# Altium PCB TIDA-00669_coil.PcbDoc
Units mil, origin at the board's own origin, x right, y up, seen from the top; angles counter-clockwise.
Board outline 2510.03 x 1760.03 mil, 2 copper layers (Top Layer, Bottom Layer), stack 62 mil thick; 13 components, 5 nets, 9 pads, 0 vias.
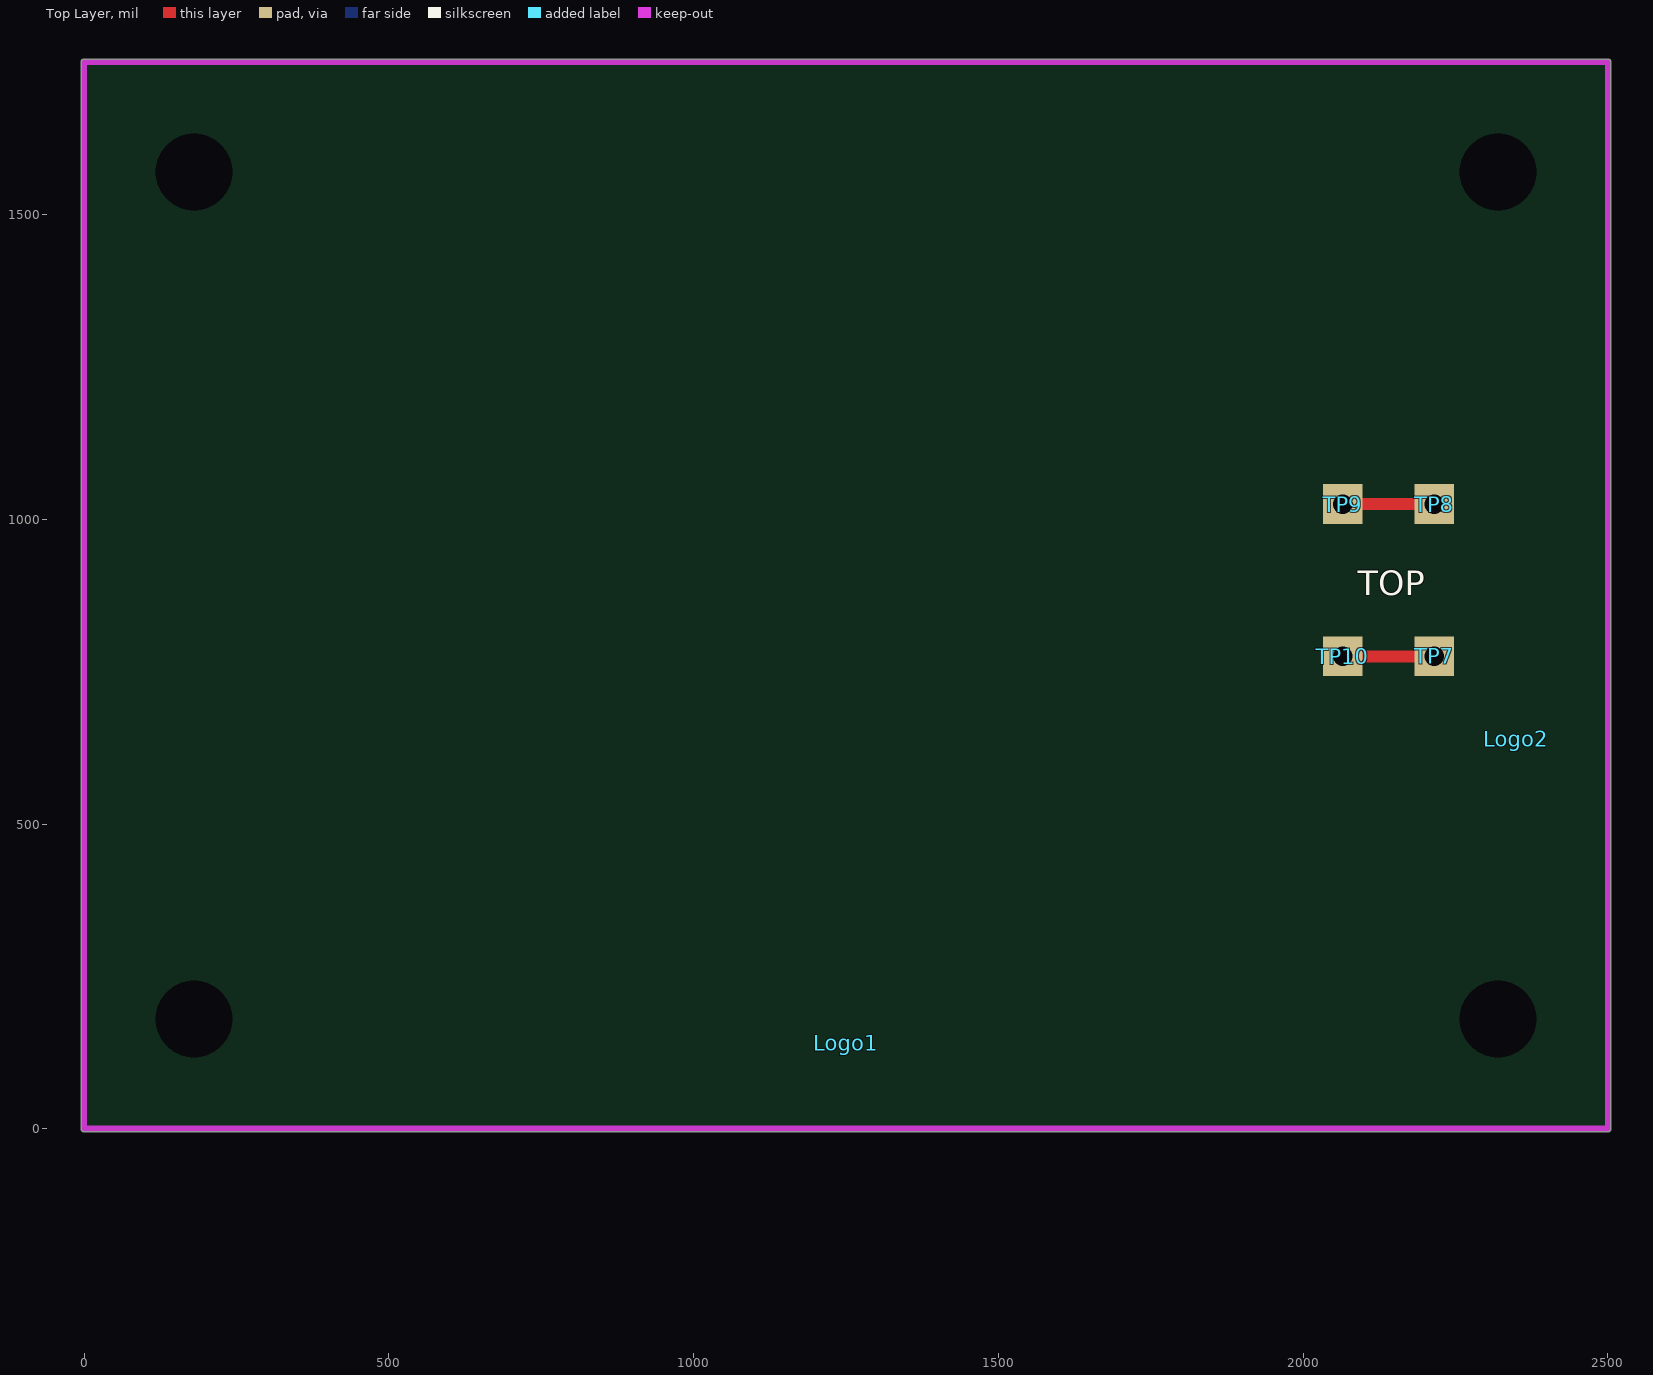
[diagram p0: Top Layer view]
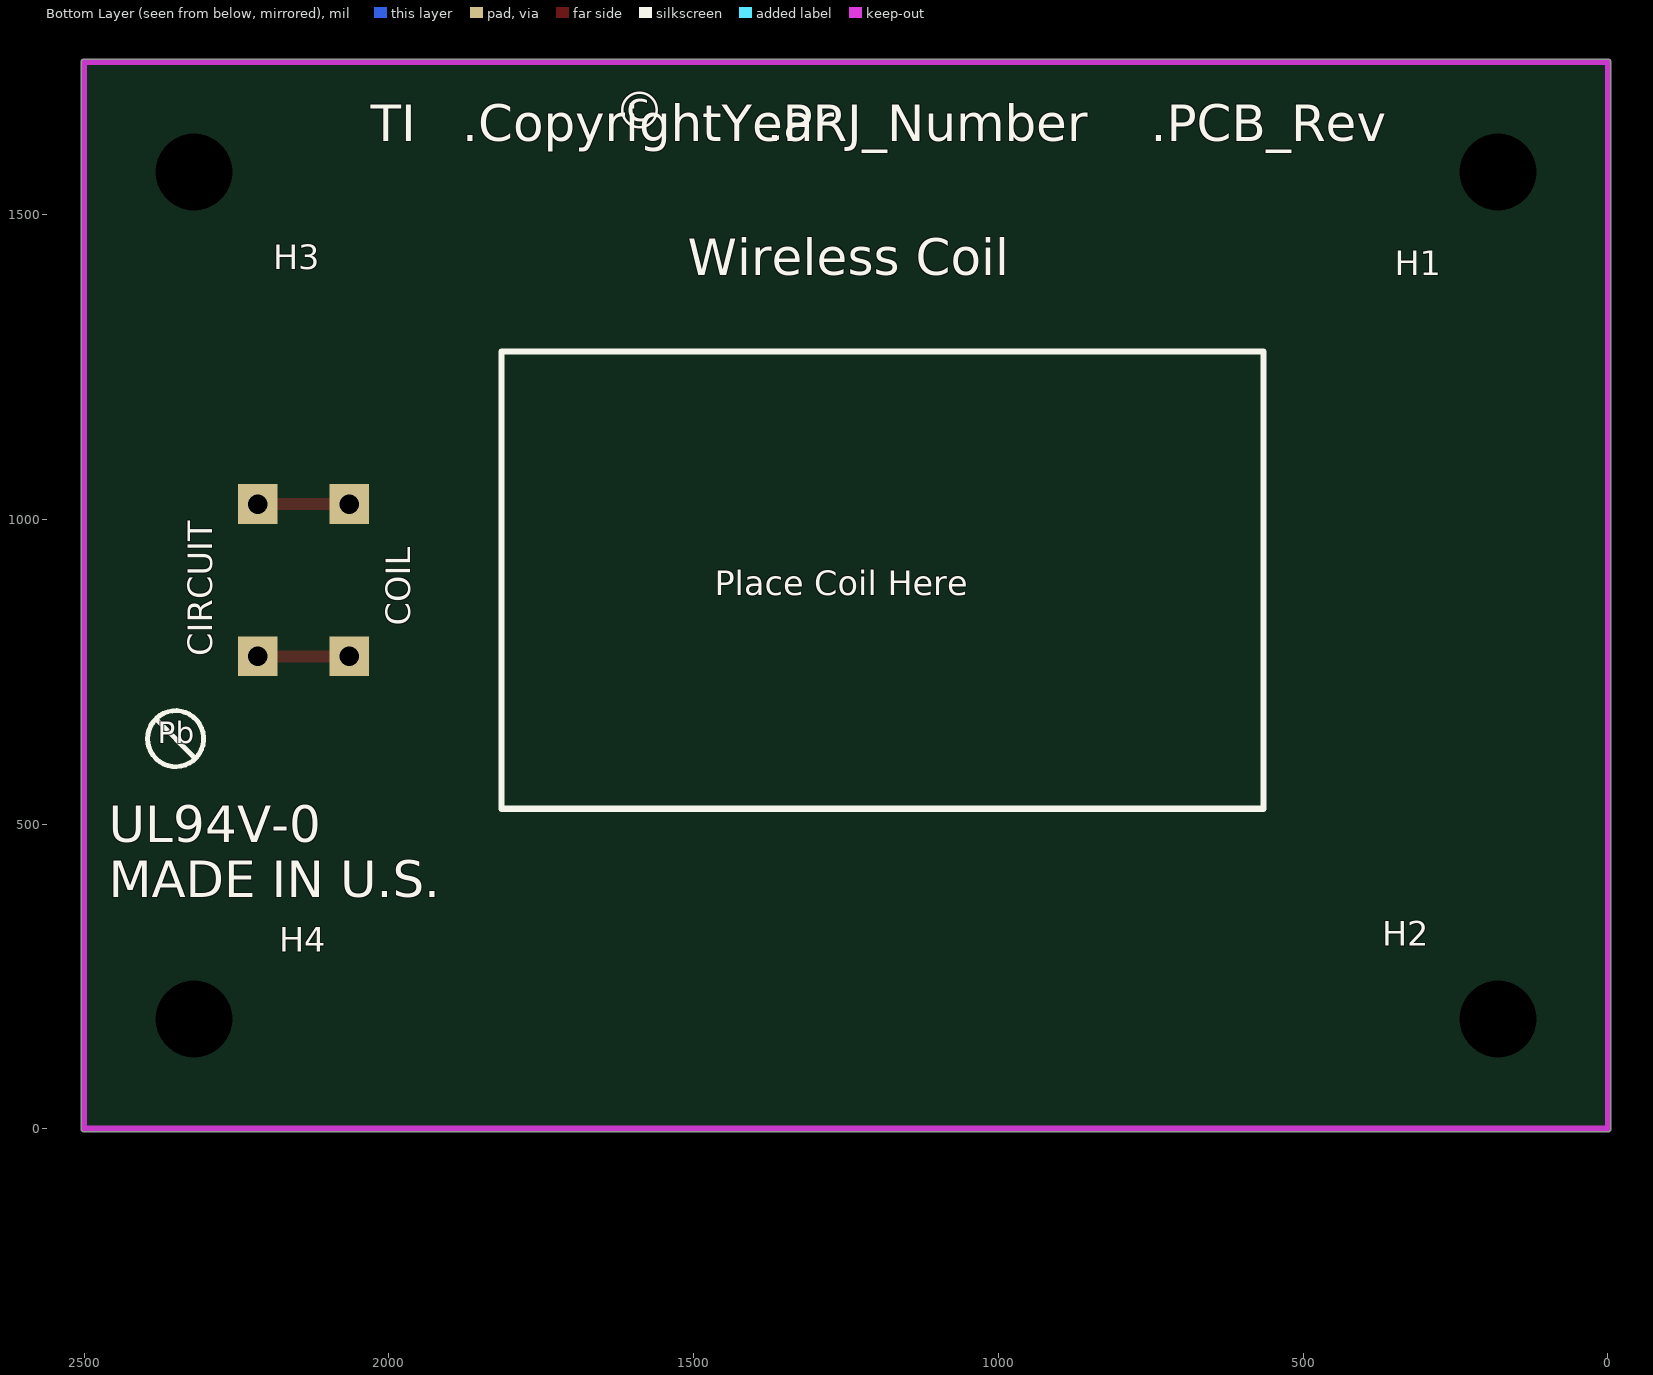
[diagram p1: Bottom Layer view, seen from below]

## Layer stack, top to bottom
Top Solder: solder mask 0.4, Solder Resist, Dk 3.5
Top Layer: signal copper 1.4
Dielectric1: core 59.2, FR-4, Dk 4.8
Bottom Layer: signal copper 1.4
Bottom Solder: solder mask 0.4, Solder Resist, Dk 3.5

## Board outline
0,-5.02 cw(c0,0) -5.01,0 -5.01,1750 cw(c0,1750) 0,1755.01 2500,1755.01 cw(c2500,1750) 2505.01,1750 2505.01,0 cw(c2500,0) 2500,-5.02

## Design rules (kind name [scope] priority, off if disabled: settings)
AcuteAngle [All] p1: minimum=4.50000000000000E+0001 checktracksonly=FALSE
AssemblyTestPointUsage [All] p1: valid=2
Clearance Clearance_Keepouts [((IsTrack Or IsArc) And Not InPoly) And IsFree and IsKeepOut vs ((IsTrack Or IsArc) And Not InPoly) And IsFree and IsKeepOut] p1: gap=0
Clearance Clearance_BoardEdge_MountingHoles [OnCopper and InComponentClass('Mounting Holes') vs IsKeepOut] p2: gap=40
Clearance Clearance_BoardEdge_Poly [OnCopper and InPoly vs IsKeepOut] p3: gap=25
Clearance Clearance_BoardEdge [OnCopper and Not InComponentClass('Logo') and not InComponentClass('FiducialMark') and not InRegion(1000,500,4000,800) and Not IsKeepout vs IsKeepOut] p4: gap=40
Clearance Clearance_Poly [InPolygon] p5: gap=12
Clearance [All] p6: gap=8
ComponentClearance ComponentClearance_MountingHoles_FiducialMarks [InComponentClass('Mounting Holes') vs InComponentClass('FiducialMark')] p1: gap=50 collisioncheckmode=3 verticalgap=10 showdistances=FALSE
ComponentClearance ComponentClearance_Shunt [InComponentClass('Header') vs InComponentClass('Shunt')] p2: gap=0 collisioncheckmode=3 verticalgap=0 showdistances=FALSE
ComponentClearance ComponentClearance_Logo [InComponentClass('Logo')] p3: gap=50 collisioncheckmode=3 verticalgap=10 showdistances=FALSE
ComponentClearance ComponentClearance_ScrewToNut [(HasFootprint('NY PMS 440 0025 PH')) vs (HasFootprint('Keystone_1902C'))] p4: gap=5 collisioncheckmode=3 verticalgap=10 showdistances=FALSE
ComponentClearance ComponentClearance_MountingHoles [InComponentClass('Mounting Holes')] p5: gap=20 collisioncheckmode=3 verticalgap=100000 showdistances=FALSE
ComponentClearance ComponentClearance_SmallPassives [HasFootprint('0201*') or HasFootprint('0402*') or HasFootprint('0508') or HasFootprint('0603*') or HasFootprint('0612') or HasFootprint('0805*') or HasFootprint('0815*') or HasFootprint('0830*') or HasFootprint('1206*') or HasFootprint('1210*') or HasFootprint('1808*') or HasFootprint('1812*') or HasFootprint('1825*') or HasFootprint('2010*') or HasFootprint('2220*') or HasFootprint('2225*') or HasFootprint('2512*') or HasFootprint('2728*') or HasFootprint('3518*') vs HasFootprint('0201*') or HasFootprint('0402*') or HasFootprint('0508') or HasFootprint('0603*') or HasFootprint('0612') or HasFootprint('0805*') or HasFootprint('0815*') or HasFootprint('0830*') or HasFootprint('1206*') or HasFootprint('1210*') or HasFootprint('1808*') or HasFootprint('1812*') or HasFootprint('1825*') or HasFootprint('2010*') or HasFootprint('2220*') or HasFootprint('2225*') or HasFootprint('2512*') or HasFootprint('2728*') or HasFootprint('3518*')] p6: gap=12 collisioncheckmode=3 verticalgap=12 showdistances=FALSE
ComponentClearance ComponentClearance_THtoSMT [IsThruComponent vs IsSMTComponent] p7: gap=12 collisioncheckmode=3 verticalgap=12 showdistances=FALSE
ComponentClearance ComponentClearance_THtoTH [IsThruComponent vs IsThruComponent] p8: gap=12 collisioncheckmode=3 verticalgap=12 showdistances=FALSE
ComponentClearance [All] p9: gap=12 collisioncheckmode=3 verticalgap=12 showdistances=FALSE
DiffPairsRouting [All] p1: maxlimit=100 minlimit=10 mostfreqgap=10 toplayer_minwidth=15 toplayer_maxwidth=15 toplayer_prefwidth=15 bottomlayer_minwidth=15 bottomlayer_maxwidth=15 bottomlayer_prefwidth=15 maxuncoupledlength=1000
FabricationTestPointUsage TestPointUsage [All] p1: valid=2 allowmultiple=FALSE
FabricationTestpoint Testpoint [All] p1: side=3 testpointundercomponent=TRUE minsize=40 maxsize=100 preferedsize=60 minholesize=0 maxholesize=40 preferedholesize=32 testpointgrid=1 allowsidetop=TRUE allowsidebottom=TRUE usegrid=TRUE gridtolerance=0.01
FanoutControl Fanout_LCC [IsLCC] p1: bgadir=Out bgaviamode=Centered fanoutstyle=Auto fanoutdirection=Alternating viagrid=1 // Fanout_LCC (Default Rule)
FanoutControl Fanout_BGA [IsBGA] p2: bgadir=Out bgaviamode=Centered fanoutstyle=Auto fanoutdirection=Alternating viagrid=1 // Fanout_BGA (Default Rule)
FanoutControl Fanout_Default [All] p4: bgadir=Out bgaviamode=Centered fanoutstyle=Auto fanoutdirection=Alternating viagrid=1 // Fanout_Default (Default Rule)
FanoutControl Fanout_Small [(CompPinCount < 5)] p5: bgadir=Out bgaviamode=Centered fanoutstyle=Auto fanoutdirection=OutThenIn viagrid=1 // Fanout_Small (Default Rule)
HoleSize [All] p1: absolutevalues=TRUE maxlimit=251 minlimit=8 maxpercent=80.000 minpercent=20.000
MinimumAnnularRing MinimumAnnularRing_ThermalPadVias [IsVia and InAnyComponent] p1: minimumring=5.91
MinimumAnnularRing [All] p2: minimumring=9
MinimumSolderMaskSliver MinimumSolderMaskSliver_Logo [InComponentClass('Logo') vs InComponentClass('Logo')] p1: minsoldermaskwidth=0.7
MinimumSolderMaskSliver [All] p2: minsoldermaskwidth=3.94
PlaneConnect [All] p1: planeconnectstyle=Relief reliefexpansion=10 reliefentries=4 reliefconductorwidth=10 reliefairgap=10
PolygonConnect [All] p1: connectstyle=Relief reliefconductorwidth=10 reliefentries=4 polygonreliefangle="90 Angle" airgapwidth=10
RoutingVias ThermalPadVias [IsVia and InAnyComponent] p1: holewidth=7.87 width=19.68 viastyle="Through Hole" minholewidth=7.87 minwidth=19.68 maxholewidth=12.99 maxwidth=23.62
RoutingVias [All] p2: holewidth=16 width=34 viastyle="Through Hole" minholewidth=7.87 minwidth=26 maxholewidth=40 maxwidth=65
SilkToBoardRegionClearance [Not ((IsComment or IsDesignator) And (Hide <> 'False')) and not InRegion(1000,500,4000,800)] p1:
SilkToSilkClearance SilkToSilkClearance_Pb-FreeLogo [(HasFootprint('Pb-Free_Overlay_Medium') OR HasFootprint('Pb-Free_Overlay_Small')) vs (HasFootprint('Pb-Free_Overlay_Medium') OR HasFootprint('Pb-Free_Overlay_Small'))] p1: silktosilkclearance=0
SilkToSilkClearance [All] p2: silktosilkclearance=5
SilkToSolderMaskClearance "Silk to Solder Mask Opening" [All] p1: minsilkscreentomaskgap=1 clearancetoexposedcopper=FALSE
SolderMaskExpansion [All] p1: expansion=1.97
UnpouredPolygon [All] p1: allowunpoured=FALSE
Width [All] p1: maxlimit=100 minlimit=6 preferedwidth=10 checkconnectedcopper=TRUE
14 further rules are at their usual default settings.

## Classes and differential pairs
component class PR2220E1_hdw: ZZ2 ZZ3 ZZ4
component class AssemblyNote: ZZ2 ZZ3 ZZ4

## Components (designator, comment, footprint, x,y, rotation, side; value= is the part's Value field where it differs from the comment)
H1 "Comment" "NY PMS 440 0025 PH" 180,1570 r180 bottom
H2 "Comment" "NY PMS 440 0025 PH" 180,180 r180 bottom
H3 "Comment" "NY PMS 440 0025 PH" 2320,1570 r180 bottom
H4 "Comment" "NY PMS 440 0025 PH" 2320,180 r180 bottom
Logo1 "Texas Instruments" TI_Stacked_SolderMask_Small 1250,140 r180 top
Logo2 "Pb-Free Symbol" Pb-Free_Overlay_Small 2350,640 r180 top
TP7 "STD" TP-032 2215,775 r0 top
TP8 "STD" TP-032 2215,1025 r0 top
TP9 "STD" TP-032 2065,1025 r0 top
TP10 "STD" TP-032 2065,775 r0 top
ZZ2 "These assemblies are ESD sensitive, ESD precautions shall be observed." AssemblyNote 185,3829.11 r0 top
ZZ3 "These assemblies must be clean and free from flux and all contaminants. Use of no clean flux is not acceptable." AssemblyNote 185,3740.56 r0 top
ZZ4 "These assemblies must comply with workmanship standards IPC-A-610 Class 2, unless otherwise specified." AssemblyNote 185,3652 r0 top

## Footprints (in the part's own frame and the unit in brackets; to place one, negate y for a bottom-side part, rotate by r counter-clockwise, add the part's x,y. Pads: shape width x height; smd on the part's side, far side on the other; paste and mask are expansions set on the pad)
AssemblyNote [mil] "Assembly Note"
"NY PMS 440 0025 PH" [mm] "4-40 nylon screw and mounting hole"
  round 0 hole 3.2 unplated: 1(0,0)
  body extent -3.3,-3.3 3.3,3.3, height 2.69
Pb-Free_Overlay_Small [mil]
TI_Stacked_SolderMask_Small [mil]
  rect 900x250 on Bottom Overlay paste-125 mask-125: 0(0,0)
TP-032 [mil]
  rect 65x65 hole 32: 1(0,0)

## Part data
Logo1: library part TI_Logo, "Texas Instrument Corporate Signature"
Logo2: library part Pb-Free
TP7 TP8 TP9 TP10: "Test Point, O.032 Hole"
ZZ2 ZZ3 ZZ4: library part AssemblyNote

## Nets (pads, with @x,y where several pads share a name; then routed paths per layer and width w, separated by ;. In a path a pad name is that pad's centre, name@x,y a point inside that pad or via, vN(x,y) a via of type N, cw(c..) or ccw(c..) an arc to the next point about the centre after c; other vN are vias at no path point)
+3.3V: 
+5V: 
GND: 
VBAT_OK: 
VBAT_OK_ALT: 
pads on no net: H1.1 H2.1 H3.1 H4.1 Logo1.0 TP7.1 TP8.1 TP9.1 TP10.1
copper on no net: | length 310
  Top Layer w20: 2065,1025 2145,1025 2215,1025 ; 2080,775 2160,775 ; 2150,775 2230,775

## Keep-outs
Keep-Out Layer:
  lines w10: 0,0 2500,0 ; 0,0 0,1750 ; 0,0 2500,0 ; 0,1750 2500,1750 ; 0,1750 2500,1750 ; 2500,0 2500,1750 ; 2500,0 2500,1750
  text ".Layer_Name" at 577,-858.49 h60

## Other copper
Top Layer:
  text ".Layer_Name" at 577,-858.49 h60
Bottom Layer:
  text ".Layer_Name" at 577,-858.49 h60
Multi-Layer:
  text "VERY IMPORTANT: The only copper on PCB is for the wire holes and the coil. No extra copper is allowed." at -130,1970 h100

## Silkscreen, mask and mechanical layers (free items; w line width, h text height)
Top Overlay:
  text "TOP" at 2090,875 h40
  text ".Layer_Name" at 577,-858.49 h60
Bottom Overlay:
  lines w10: 565,525 1815,525 1815,1275 565,1275 565,525
  text ".PCB_Rev" at 750,1620 h60
  text ".PRJ_Number" at 1380,1620 h60
  text "©" at 1630,1620 h105
  text ".CopyrightYear" at 1880,1620 h60
  text "TI" at 2030,1620 h60
  text "Wireless Coil" at 1510,1400 h60
  text "Place Coil Here" at 1465,875 h40
  text "COIL" at 1965,825 h40 r270
  text "CIRCUIT" at 2290,775 h40 r270
  text "UL94V-0" at 2460,470 h60
  text "MADE IN U.S." at 2460,380 h60
  text ".Layer_Name" at 577,-858.49 h60
Top Paste:
  text ".Layer_Name" at 577,-858.49 h60
Bottom Paste:
  text ".Layer_Name" at 577,-858.49 h60
Top Solder:
  text ".Layer_Name" at 577,-858.49 h60
  text ".Layer_Name" at 577,-858.49 h60
Bottom Solder:
  text ".Layer_Name" at 577,-858.49 h60
Drill Guide:
  text ".Layer_Name" at 577,-858.49 h60
M1 Board Outline:
  lines w10: 0,0 2500,0 2500,1750 0,1750 0,0
  text ".Layer_Name" at 577,-858.49 h60
M2 Board Dimensions:
  rectangle: 0,-275 125,-150
  rectangle: 125,-400 500,-275
  lines w7: 0,-275 1000,-275 ; 0,-150 0,-400 1000,-400 1000,-150 ; 125,-400 125,-150 ; 250,-400 250,-150 ; 500,-400 500,-150 ; 750,-400 750,-150
  text ".Layer_Name" at 577,-858.49 h60
M3 3D STEP Top:
  text ".Layer_Name" at 577,-858.49 h60
M4 3D STEP Bottom:
  lines w10: 6984.8,1433.6 7005,1433.6 ; 6984.9,1152.7 7005.1,1152.7
  text ".Layer_Name" at 577,-858.49 h60
M5 Assembly Top:
  lines w10: -292,-930.17 6308,-930.17 ; -292,-726.83 6310,-726.83 ; -292,-523.5 -292,-1133.5 3713,-1133.5 6310,-1133.5 6310,-523.5 -291.5,-523.5 -291.5,-1133.5 1284,-1133.5 ; 2173,-1133.5 2173,-523.5 ; 3440,-726.83 3440,-523.5 ; 4280,-726.83 4280,-523.5 ; 4902,-1140 4902,-937.17
  text "COMPONENTS MARKED 'DNP' SHOULD NOT BE POPULATED." at 1153.5,-318.5 h60
  text "ASSEMBLY VARIANT:" at 1153,-434 h60
  text ".VariantName" at 2189,-434 h60
  text "PCB VIEWED FROM TOP SIDE" at -228.5,-655.67 h60
  text "BOARD #:" at 2248,-655.67 h60
  text ".PRJ_Number" at 2793.5,-655.67 h60
  text "REV:" at 3638,-655.67 h60
  text ".PCB_Rev" at 3929.5,-655.67 h60
  text "SVN REV:" at 4476,-655.67 h60
  text ".VersionControl_RevNumber" at 4982,-655.67 h60
  text "PLOT NAME =" at -228.5,-1064.34 h60
  text ".plot_File_Name" at 577,-1064.34 h60
  text "GENERATED    :" at 2250,-1064.34 h60
  text ".Print_Date" at 3119.5,-1064.34 h60
  text ".Print_Time" at 3848.5,-1064.34 h60
  text "TEXAS INSTRUMENTS" at 5113,-1064.34 h60
M6 Assembly Bottom:
  lines w10: -292.5,-727.33 6309.5,-727.33 ; -290.5,-930.67 6309.5,-930.67 ; 1115.5,-1140.5 1115.5,-937.67 ; 1737.5,-727.33 1737.5,-524 ; 2577.5,-727.33 2577.5,-524 ; 3844.5,-1134 3844.5,-524 ; 4733.5,-1134 6309,-1134 6309,-524 -292.5,-524 -292.5,-1134 2304.5,-1134 6309.5,-1134 6309.5,-524
  text "COMPONENTS MARKED 'DNP' SHOULD NOT BE POPULATED." at 6102,-318 h60
  text ".VariantName" at 5058,-434 h60
  text "ASSEMBLY VARIANT:" at 6097,-434 h60
  text ".VersionControl_RevNumber" at 1035.5,-656.17 h60
  text "SVN REV:" at 1541.5,-656.17 h60
  text ".PCB_Rev" at 2088,-656.17 h60
  text "REV:" at 2379.5,-656.17 h60
  text ".PRJ_Number" at 3224,-656.17 h60
  text "BOARD #:" at 3769.5,-656.17 h60
  text "PCB VIEWED FROM BOTTOM SIDE" at 6246,-656.17 h60
  text "TEXAS INSTRUMENTS" at 904.5,-1064.84 h60
  text ".Print_Time" at 2169,-1064.84 h60
  text ".Print_Date" at 2898,-1064.84 h60
  text "GENERATED    :" at 3767.5,-1064.84 h60
  text ".plot_File_Name" at 5440.5,-1064.84 h60
  text "PLOT NAME =" at 6246,-1064.84 h60
M9 Title Sheet:
  drawing of 57 lines, arcs and shapes, not listed
  text "1" at 739.84,8036.5 h70
  text "2" at 3235.5,8036.5 h70
  text "3" at 5724.84,8036.5 h70
  text "4" at 8231.51,8036.5 h70
  text "5" at 10730.5,8036.5 h70
  text "6" at 13235.5,8036.5 h70
  text "A" at -416.5,6893.5 h70
  text "A" at 14383.5,6893.5 h70
  text "B" at -416.5,4513.5 h70
  text "B" at 14383.5,4513.5 h70
  text "C" at -416.5,2138.5 h70
  text "C" at 14383.5,2138.5 h70
  text "PROJECT TITLE:" at 11343.5,277.5 h45
  text ".PRJ_Title" at 11393.5,144.17 h70
  text "DESIGNED FOR:" at 11343.5,-23.5 h45
  text ".PRJ_Customer" at 11393.5,-163.5 h70
  text "D" at -416.5,-231.5 h70
  text "D" at 14383.5,-231.5 h70
  text "FILE NAME:" at 11343.5,-323.5 h45
  text ".PCB_File_Name_No_Path" at 11393.5,-443.5 h70
  text "Texas Instruments (TI) and/or its licensors do not warrant the accuracy or completeness of this specification" at 6374,-605.34 h45
  text "ENGINEER:" at 11343.5,-613.5 h45
  text "LAYOUT BY:" at 12848.5,-613.5 h45
  text "or any information contained therein. TI and/or its licensors do not warrant that this design will meet" at 6329.01,-718 h45
  text ".PRJ_Engineer" at 11393.5,-768.49 h70
  text ".PCB_Layout" at 12899,-768.49 h70
  text "the specifications, will be suitable for your application or fit for any particular purpose, or will operate in" at 6329.01,-830.67 h45
  text ".Layer_Name" at 577,-858.49 h60
  text "ALTIUM DESIGNER VERSION:" at 12848.5,-923.5 h45
  text "an implementation. TI and/or its licensors do not warrant that the design is production worthy. You should" at 6329.01,-943.33 h45
  text "completely validate and test your design implementation to confirm the system functionality for your application." at 6374,-1056 h45
  text ".print_Scale" at 11393.5,-1056.83 h70
  text ".Application_BuildNumber" at 12899,-1056.83 h70
  text "1" at 739.84,-1263.5 h70
  text "2" at 3235.5,-1263.5 h70
  text "3" at 5724.84,-1263.5 h70
  text "4" at 8231.51,-1263.5 h70
  text "5" at 10730.5,-1263.5 h70
  text "6" at 13235.5,-1263.5 h70
M10 Fab Notes:
  drawing of 185 lines, arcs and shapes, not listed
  text "DESIGN INFORMATION" at 12381.02,5910 h60
  text "MIN. TRACK WIDTH:" at 11736.46,5730 h60
  text "8" at 12832.7,5730 h60
  text "MIL" at 12987.46,5730 h60
  text "MIN. CLEARANCE:" at 11736.46,5598 h60
  text "0.2" at 12772.7,5598 h60
  text "mm" at 12987.46,5598 h60
  text "MIN. VIA PAD SIZE:" at 11736.46,5466 h60
  text "24" at 12802.71,5466 h60
  text "MIL" at 12987.46,5466 h60
  text "0.05mm (2MIL)" at 12431.46,5324.29 h60
  text "MINIMUM ANNULAR RING" at 11407.23,5320 h60
  text "EXTERNAL" at 13139.46,5320 h60
  text "PER" at 11607.23,5202 h60
  text "IPC-D-275 CLASS 2 LEVEL C" at 11827.23,5202 h60
  text "MIL, HOLES" at 13315.46,5089.71 h60
  text "+/-" at 12923,5089 h60
  text "+/-" at 13777,5089 h60
  text "REGISTRATION TOLERANCES:" at 11407.23,5084 h60
  text "METAL" at 12607,5084 h60
  text "5" at 13183.2,5084 h60
  text "3" at 14016.2,5084 h60
  text "MIL" at 14132.46,5084 h60
  text "MATERIAL:" at 11332.46,4874.54 h60
  text "FR-4 High Tg" at 12318.9,4734.21 h60
  text "FR-408" at 11753.46,4725.64 h60
  text "X" at 12165.46,4725.64 h60
  text "OTHER" at 13241.46,4725.64 h60
  text "62 MIL (1.6mm) +/-10%" at 12073.56,4562.92 h60
  text "THICKNESS:" at 11407.23,4558.64 h60
  text "X" at 11945.4,4558.64 h60
  text "OTHER" at 13358.46,4558.64 h60
  text "TOLERANCE:" at 11407.23,4400.64 h60
  text "X" at 12246.53,4400.64 h60
  text "ANSI IPC-6012 TYPE 3 CLASS 2" at 12433.48,4400.64 h60
  text "OTHER +/-" at 12433.46,4244.64 h60
  text "BOW & TWIST:" at 11407.23,4087.64 h60
  text "X" at 12246.53,4087.64 h60
  text "ANSI IPC-6012 TYPE 3 CLASS 2" at 12433.48,4087.64 h60
  text "OTHER +/-" at 12433.46,3929.13 h60
  text "DRILLING:" at 11332.46,3790.64 h60
  text "REFERENCE:" at 11407.23,3673.64 h60
  text "X" at 12055.46,3673.64 h60
  text "AS SHOWN" at 12242.46,3673.64 h60
  text "X" at 12956.46,3673.64 h60
  text "NC_DRILL FILES" at 13093.46,3673.64 h60
  text "PTH MIN COPPER THICKNESS:" at 11407.23,3515.64 h60
  text "X" at 12757.46,3515.64 h60
  text "1MIL" at 12894.46,3515.64 h60
  text "OTHER" at 13391.46,3515.64 h60
  text "BOARD FINISH:" at 11332.46,3356.64 h60
  text "SILKSCREEN:" at 11487.68,3238.64 h60
  text "X" at 12436.46,3238.64 h60
  text "TOP" at 12562.46,3238.64 h60
  text "X" at 12946.46,3238.64 h60
  text "BOTTOM" at 13073.46,3238.64 h60
  text "SILKSCREEN COLOR:" at 11487.68,3071.64 h60
  text "X" at 12435.42,3071.64 h60
  text "WHITE" at 12562.46,3071.64 h60
  text "OTHER" at 13073.46,3071.64 h60
  text "SOLDER RESIST COLOR:" at 11487.68,2901.64 h60
  text "X" at 12055.42,2742.44 h60
  text "GREEN" at 12182.46,2742.44 h60
  text "BLUE" at 12773.46,2742.44 h60
  text "OTHER" at 13311.46,2742.44 h60
  text "IMMERSION GOLD (ENIG)" at 12393.46,2553.92 h60
  text "ENEPIG" at 13731,2550.64 h60
  text "SURFACE FINISH:" at 11332.46,2549.64 h60
  text "X" at 12206.51,2549.64 h60
  text "IMM. TIN/SILVER OR EQUIV" at 11662,2392.64 h60
  text "OTHER" at 13093.46,2392.64 h60
  text "ARRAY/PANEL:" at 11332.46,2213.64 h60
  text "CUT AND TRIM PER MECH LAYER 1" at 12393.46,2209.35 h60
  text "N.C. ROUTE" at 12393.46,2057.64 h60
  text "X" at 13072.46,2057.64 h60
  text "V. SCORE" at 13259.46,2057.64 h60
  text "CERTIFICATION:" at 11332.46,1920.64 h60
  text "MATERIALS AND WORKMANSHIP FOR ALL PCBS" at 12057.46,1920.64 h60
  text "TO MEET OR EXCEED THE REQUIREMENTS OF:" at 12057.46,1822.64 h60
  text "X" at 11683.96,1686.13 h60
  text "ANSI IPC-A-600F CLASS ->" at 11822.96,1686.13 h60
  text "X" at 13462.02,1686.13 h60
  text "2" at 13580.96,1686.14 h60
  text "1" at 13265.96,1684.64 h60
  text "3" at 13934.96,1684.64 h60
  text "X" at 11686.02,1526.64 h60
  text "UL 94V-0" at 11822.96,1526.64 h60
  text "X" at 12498.02,1526.64 h60
  text "RoHS" at 12634.96,1526.64 h60
  text "OTHER" at 13279.36,1526.64 h60
  text "PER ORDER" at 13676.42,1526.64 h60
  text "ADDITIONAL REQUIREMENTS:" at 11332.46,1385.64 h60
  text "MICROSECTION:" at 11407.23,1270.64 h60
  text "YES" at 12312.96,1270.64 h60
  text "REQUIRED" at 13174.46,1114.49 h60
  text "BARE BOARD ELEC. TEST:" at 11407.23,1111.64 h60
  text "NONE" at 12712.96,1111.64 h60
  text "X" at 13047.46,1111.64 h60
  text "PER ORDER" at 13766.46,1111.64 h60
  text "MANUFACTURER'S UL:" at 11407.23,954.64 h60
  text "RAIL" at 12572.96,950.35 h60
  text "METAL" at 13064.77,950.35 h60
  text "X" at 13440,950 h60
  text "SILK" at 13576.46,950.35 h60
  text ".Layer_Name" at 577,-858.49 h60
M11 Gerber Information:
  lines w10: -292,-930.17 6308,-930.17 ; -292,-726.83 6310,-726.83 ; -292,-523.5 -292,-1133.5 3713,-1133.5 6310,-1133.5 6310,-523.5 -291.5,-523.5 -291.5,-1133.5 1284,-1133.5 ; 2173,-1133.5 2173,-523.5 ; 3440,-726.83 3440,-523.5 ; 4280,-726.83 4280,-523.5 ; 4902,-1140 4902,-937.17
  text "ALL ARTWORK VIEWED FROM TOP SIDE" at -228.5,-655.67 h60
  text "BOARD #:" at 2248,-655.67 h60
  text ".PRJ_Number" at 2793.5,-655.67 h60
  text "REV:" at 3638,-655.67 h60
  text ".PCB_Rev" at 3929.5,-655.67 h60
  text "SVN REV:" at 4476,-655.67 h60
  text ".VersionControl_RevNumber" at 4982,-655.67 h60
  text "LAYER NAME =" at -228.5,-858.49 h60
  text "PLOT NAME =" at -228.5,-1064.34 h60
  text ".plot_File_Name" at 577,-1064.34 h60
  text "GENERATED    :" at 2250,-1064.34 h60
  text ".Print_Date" at 3119.5,-1064.34 h60
  text ".Print_Time" at 3848.5,-1064.34 h60
  text "TEXAS INSTRUMENTS" at 5113,-1064.34 h60
M12 Stackup:
  drawing of 191 lines, arcs and shapes, not listed
  text "Layer" at 9790.58,7830 h60
  text "Name" at 10200.49,7830 h60
  text "Material" at 11130.23,7830 h60
  text "Thickness" at 11990,7830 h60
  text "Constant" at 12639.84,7830 h60
  text "Board Layer Stack" at 13209.7,7830 h60
  text "1" at 9790.58,7710 h60
  text "Top Overlay" at 10200.49,7710 h60
  text "2" at 9790.58,7590 h60
  text "Top Solder" at 10200.49,7590 h60
  text "Solder Resist" at 11130.23,7590 h60
  text "0.40mil" at 11990,7590 h60
  text "3.5" at 12639.84,7590 h60
  text "3" at 9790.58,7470 h60
  text "Top Layer" at 10200.49,7470 h60
  text "Copper" at 11130.23,7470 h60
  text "1.40mil" at 11990,7470 h60
  text "4" at 9790.58,7350 h60
  text "Dielectric1" at 10200.49,7350 h60
  text "FR-4" at 11130.23,7350 h60
  text "59.20mil" at 11990,7350 h60
  text "4.8" at 12639.84,7350 h60
  text "5" at 9790.58,7230 h60
  text "Bottom Layer" at 10200.49,7230 h60
  text "Copper" at 11130.23,7230 h60
  text "1.40mil" at 11990,7230 h60
  text "6" at 9790.58,7110 h60
  text "Bottom Solder" at 10200.49,7110 h60
  text "Solder Resist" at 11130.23,7110 h60
  text "0.40mil" at 11990,7110 h60
  text "3.5" at 12639.84,7110 h60
  text "7" at 9790.58,6990 h60
  text "Bottom Overlay" at 10200.49,6990 h60
  text ".Layer_Name" at 577,-858.49 h60
M13 Component Bodies Top:
  text ".Layer_Name" at 577,-858.49 h60
M14 Component Bodies Bottom:
  text ".Layer_Name" at 577,-858.49 h60
M15 Courtyards Top:
  text ".Layer_Name" at 577,-858.49 h60
M16 Courtyards Bottom:
  text ".Layer_Name" at 577,-858.49 h60
Drill Drawing:
  circle w1: c5572.82,3071.27 r14.95
  circle w1: c5572.82,3071.27 r24.92
  lines w1: 5547.91,3208.31 5560.37,3208.31 5572.82,3195.85 5585.28,3208.31 5597.74,3208.31 5585.28,3220.77 5597.74,3233.22 5585.28,3233.22 5572.82,3245.68 5560.37,3233.22 5547.91,3233.22 5560.37,3220.77 5547.91,3208.31 ; 5557.88,3213.29 5565.35,3213.29 5572.82,3205.82 5580.3,3213.29 5587.77,3213.29 5580.3,3220.77 5587.77,3228.24 5580.3,3228.24 5572.82,3235.72 5565.35,3228.24 5557.88,3228.24 5565.35,3220.77 5557.88,3213.29
  lines w12: 5480,3001.5 7598.44,3001.5 ; 5480,3300.5 7598.44,3300.5 ; 5850.51,2852 5850.51,3450 ; 6207.67,2852 6207.67,3450 ; 6869.15,2852 6869.15,3450 ; 7153.35,2852 7153.35,3450 ; 5480,2852 7598.44,2852 7598.44,3450 5480,3450 5480,2852
  text "Symbol" at 5569.7,3345.35 h72
  text "Quantity" at 5895.36,3345.35 h72
  text "Finished Hole Size" at 6252.52,3345.35 h72
  text "Plated" at 6914,3345.35 h72
  text "Hole Type" at 7198.2,3345.35 h72
  text "4" at 5895.36,3195.85 h60
  text "125.98mil (3.200mm)" at 6252.52,3195.85 h60
  text "NPTH" at 6914,3195.85 h60
  text "Round" at 7198.2,3195.85 h60
  text "4" at 5895.36,3046.35 h60
  text "32.00mil (0.813mm)" at 6252.52,3046.35 h60
  text "PTH" at 6914,3046.35 h60
  text "Round" at 7198.2,3046.35 h60
  text "8 Total" at 5895.36,2896.85 h60
  text ".Layer_Name" at 577,-858.49 h60

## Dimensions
0,0 to 2500,0 on Top Layer
0,1750 to 0,0 on Top Layer
0,-400 to 1000,-400 on M2 Board Dimensions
